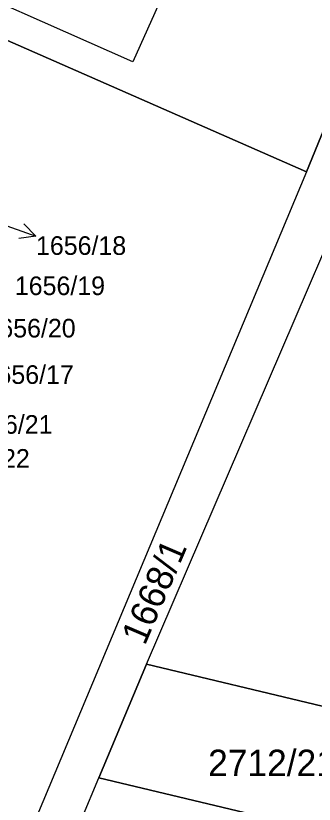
# Model space of a CAD drawing. Extents: x -596024 to -594475, y -1163820 to -1161957.
# Drawn here: x -595624.2 to -595605, y -1162105.4 to -1162054.6 of the extents above; entities that cross this region are included whole.
import ezdxf

# ---------------------------------------------------------------- set-up
doc = ezdxf.new("R2010")
doc.units = 0
for name, color, linetype in [('Level 1', 7, 'Continuous'), ('Level 4', 7, 'Continuous'), ('Level 57', 7, 'Continuous'), ('Level 60', 7, 'Continuous'), ('Vrstva 60', 7, 'Continuous')]:
    doc.layers.add(name, color=color, linetype=linetype)

msp = doc.modelspace()

# ---------------------------------------------------------------- linework, layer by layer
at = {"layer": 'Level 1'}
for points in [[(-595605.47, -1162064.69), (-595572.78, -1161984.7), (-595561.957, -1161956.88)], [(-595615.75, -1162096.4), (-595602.7, -1162066), (-595591.42, -1162038.27)], [(-595631.07, -1162051.18), (-595627.55, -1162043.32), (-595613.13, -1162049.78), (-595616.64, -1162057.6), (-595631.07, -1162051.18)], [(-595605.47, -1162064.69), (-595646.62, -1162046.56)], [(-595605.47, -1162064.69), (-595636.59, -1162139.13)], [(-595615.75, -1162096.4), (-595618.81, -1162103.71)], [(-595604.46, -1162099.1), (-595615.75, -1162096.4)], [(-595625.39, -1162119.44), (-595618.81, -1162103.71)], [(-595618.81, -1162103.71), (-595607.58, -1162106.39)]]:
    msp.add_lwpolyline(points, dxfattribs=at)
at = {"layer": 'Level 57'}
msp.add_line((-595625.685, -1162067.819), (-595622.86, -1162068.83), dxfattribs=at)
msp.add_lwpolyline([(-595623.633, -1162068.022), (-595622.86, -1162068.83), (-595623.97, -1162068.964)], dxfattribs=at)
at = {"layer": 'Level 60'}
for points in [[(-595591.42, -1162038.27), (-595586.51, -1162039.43), (-595579.93, -1162041.11), (-595582.47, -1162047.97), (-595604.46, -1162099.1), (-595615.75, -1162096.4), (-595602.7, -1162066)], [(-595631.07, -1162051.18), (-595627.55, -1162043.32), (-595613.13, -1162049.78), (-595616.64, -1162057.6)], [(-595604.46, -1162099.1), (-595597.3, -1162100.8), (-595600.24, -1162108.12), (-595607.58, -1162106.39), (-595618.81, -1162103.71), (-595615.75, -1162096.4)], [(-595618.81, -1162103.71), (-595607.58, -1162106.39), (-595614.31, -1162122.04), (-595625.39, -1162119.44)]]:
    msp.add_lwpolyline(points, close=True, dxfattribs=at)
msp.add_lwpolyline([(-595698.23, -1162081.48), (-595688.29, -1162059.74), (-595687.27, -1162058.23), (-595685.95, -1162057.58), (-595683.76, -1162058.04), (-595673.56, -1162062.13), (-595669.16, -1162051.9), (-595666.53, -1162053.03), (-595651.98, -1162059.14), (-595650.49, -1162054.85), (-595667.27, -1162047.5), (-595664.46, -1162040.96), (-595663.57, -1162041.38), (-595662.76, -1162040.03), (-595661.92, -1162040.41), (-595661.68, -1162039.89), (-595653.01, -1162043.65), (-595648.38, -1162045.78), (-595646.62, -1162046.56), (-595605.47, -1162064.69), (-595636.59, -1162139.13), (-595651.51, -1162132.01), (-595692.37, -1162113.74), (-595703.38, -1162138.38)], dxfattribs=at)
at = {"layer": 'Vrstva 60'}
for points in [[(-595558.702, -1161956.88), (-595561.957, -1161956.88), (-595572.78, -1161984.7), (-595605.47, -1162064.69), (-595636.59, -1162139.13), (-595645.59, -1162159.83), (-595642.61, -1162160.49), (-595632.03, -1162135.3), (-595625.39, -1162119.44), (-595618.81, -1162103.71), (-595615.75, -1162096.4), (-595602.7, -1162066), (-595591.42, -1162038.27), (-595580.65, -1162012.51), (-595563.95, -1161970.42), (-595560.71, -1161962.17)], [(-595613.13, -1162049.78), (-595616.64, -1162057.6), (-595631.07, -1162051.18), (-595627.55, -1162043.32)]]:
    msp.add_lwpolyline(points, close=True, dxfattribs=at)
msp.add_lwpolyline([(-595646.62, -1162046.56), (-595605.47, -1162064.69), (-595572.78, -1161984.7)], dxfattribs=at)

# ---------------------------------------------------------------- texts
at = {"layer": 'Level 4'}
msp.add_text('1668/1', height=1.7, rotation=66.7673, dxfattribs=at).set_placement((-595615.86, -1162095.24))
msp.add_text('2712/212', height=1.7, dxfattribs=at).set_placement((-595611.79, -1162103.6))
at = {"layer": 'Level 57'}
for s, p in [('1656/18', (-595622.86, -1162070.03)), ('1656/19', (-595624.22, -1162072.62)), ('1656/20', (-595626.11, -1162075.35)), ('1656/17', (-595626.23, -1162078.34)), ('1656/21', (-595627.6, -1162081.55)), ('1656/22', (-595629.06, -1162083.74))]:
    msp.add_text(s, height=1.2, dxfattribs=at).set_placement(p)

doc.saveas('drawing.dxf')
